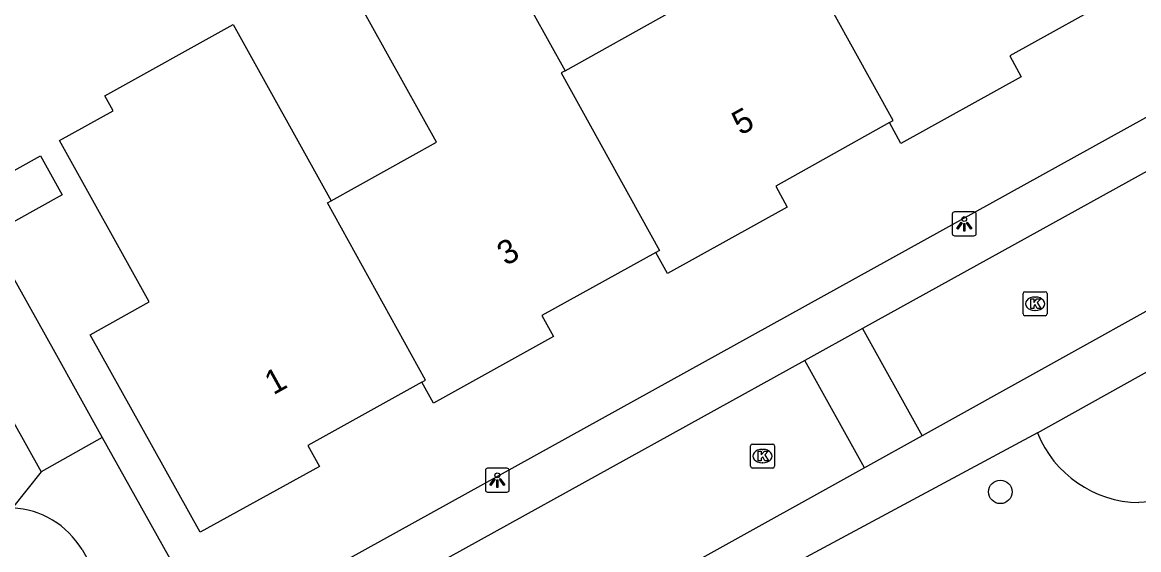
# Model space of a CAD drawing. Extents: x 159628 to 160723, y 388176 to 389416.
# Drawn here: x 160211.83 to 160258.4, y 388442.94 to 388464.92 of the extents above; entities that cross this region are included whole.
import ezdxf

# ---------------------------------------------------------------- set-up
doc = ezdxf.new("R2010")
doc.units = 0
for name, color, linetype in [('IMGEO_Boom', 7, 'Continuous'), ('IMGEO_Groenvoorziening', 7, 'Continuous'), ('IMGEO_Kolk', 7, 'Continuous'), ('IMGEO_Lichtpunt', 7, 'Continuous'), ('IMGEO_Pand', 7, 'Continuous'), ('IMGEO_Pand_nummerreeks', 7, 'Continuous'), ('IMGEO_Rijbaan_lokaal_open', 7, 'Continuous'), ('IMGEO_Voetpad_halfverhard', 7, 'Continuous'), ('IMGEO_Voetpad_open', 7, 'Continuous')]:
    doc.layers.add(name, color=color, linetype=linetype)

msp = doc.modelspace()

# ---------------------------------------------------------------- linework, layer by layer
at = {"layer": 'IMGEO_Boom'}
msp.add_circle((160252.625, 388445.345), 0.489, dxfattribs=at)
at = {"layer": 'IMGEO_Groenvoorziening'}
for points in [[(160185.435, 388468.284), (160195.231, 388450.891), (160209.082, 388458.498), (160213.193, 388451.174), (160215.17, 388447.612)], [(160182.913, 388467.038), (160193.72, 388447.443), (160200.505, 388448.02), (160208.94, 388452.771), (160212.613, 388446.186)], [(160215.17, 388447.612), (160212.613, 388446.186)], [(160215.17, 388447.612), (160219.753, 388439.417)], [(160212.613, 388446.186), (160211.422, 388444.678)], [(160270.271, 388445.647), (160264.046, 388445.253), (160258.395, 388444.896)]]:
    msp.add_lwpolyline(points, dxfattribs=at)
msp.add_arc((160258.493, 388449.56), 4.665, 202.0696, 268.7972, dxfattribs=at)
at = {"layer": 'IMGEO_Kolk'}
for p, q in [((160253.574, 388452.763), (160253.574, 388453.615)), ((160253.649, 388453.689), (160254.501, 388453.689)), ((160254.062, 388453.469), (160254.087, 388453.469)), ((160254.575, 388453.615), (160254.575, 388452.763)), ((160254.085, 388452.909), (160254.06, 388452.909)), ((160254.501, 388452.689), (160253.649, 388452.689)), ((160242.209, 388446.411), (160242.209, 388447.263)), ((160242.284, 388447.337), (160243.136, 388447.337)), ((160243.21, 388447.263), (160243.21, 388446.411)), ((160242.697, 388447.117), (160242.722, 388447.117)), ((160243.136, 388446.337), (160242.284, 388446.337)), ((160242.72, 388446.557), (160242.695, 388446.557))]:
    msp.add_line(p, q, dxfattribs=at)
for points in [[(160253.574, 388452.763), (160253.574, 388453.615)], [(160253.649, 388453.689), (160254.501, 388453.689)], [(160253.895, 388453.389), (160254.018, 388453.389), (160254.018, 388453.238), (160254.148, 388453.389), (160254.312, 388453.389), (160254.166, 388453.238), (160254.319, 388452.989), (160254.167, 388452.989), (160254.082, 388453.153), (160254.018, 388453.086), (160254.018, 388452.989), (160253.895, 388452.989), (160253.895, 388453.389)], [(160254.575, 388453.615), (160254.575, 388452.763)], [(160254.501, 388452.689), (160253.649, 388452.689)], [(160242.209, 388446.411), (160242.209, 388447.263)], [(160242.284, 388447.337), (160243.136, 388447.337)], [(160243.21, 388447.263), (160243.21, 388446.411)], [(160242.53, 388447.037), (160242.653, 388447.037), (160242.653, 388446.886), (160242.783, 388447.037), (160242.947, 388447.037), (160242.801, 388446.886), (160242.954, 388446.637), (160242.802, 388446.637), (160242.717, 388446.801), (160242.653, 388446.734), (160242.653, 388446.637), (160242.53, 388446.637), (160242.53, 388447.037)], [(160243.136, 388446.337), (160242.284, 388446.337)]]:
    msp.add_lwpolyline(points, dxfattribs=at)
for centre, start, end in [((160253.651, 388453.613), 91.552, 178.448), ((160253.651, 388453.613), 91.552, 178.448), ((160254.499, 388453.613), 1.552, 88.448), ((160254.499, 388453.613), 1.552, 88.448), ((160253.651, 388452.765), 181.552, 268.448), ((160253.651, 388452.765), 181.552, 268.448), ((160254.499, 388452.765), 271.552, 358.448), ((160254.499, 388452.765), 271.552, 358.448), ((160242.286, 388447.261), 91.552, 178.448), ((160242.286, 388447.261), 91.552, 178.448), ((160243.134, 388447.261), 1.552, 88.448), ((160243.134, 388447.261), 1.552, 88.448), ((160242.286, 388446.413), 181.552, 268.448), ((160242.286, 388446.413), 181.552, 268.448), ((160243.134, 388446.413), 271.552, 358.448), ((160243.134, 388446.413), 271.552, 358.448)]:
    msp.add_arc(centre, 0.0765, start, end, dxfattribs=at)
for centre, major_axis, ratio, start_param, end_param in [((160254.061, 388453.189), (-0.387, 0.002), 0.722429, 4.712389, 7.853982), ((160254.086, 388453.189), (-0.39, 0.002), 0.717154, 1.570796, 4.712389), ((160242.696, 388446.837), (-0.387, 0.002), 0.722429, 4.712389, 7.853982), ((160242.721, 388446.837), (-0.39, 0.002), 0.717154, 1.570796, 4.712389)]:
    msp.add_ellipse(centre, major_axis=major_axis, ratio=ratio, start_param=start_param, end_param=end_param, dxfattribs=at)
at = {"layer": 'IMGEO_Lichtpunt'}
for p, q in [((160250.622, 388456.923), (160250.622, 388456.116)), ((160250.622, 388456.923), (160250.622, 388456.116)), ((160251.524, 388457.018), (160250.716, 388457.018)), ((160251.524, 388457.018), (160250.716, 388457.018)), ((160251.618, 388456.116), (160251.618, 388456.923)), ((160251.618, 388456.116), (160251.618, 388456.923)), ((160250.716, 388456.022), (160251.524, 388456.022)), ((160250.716, 388456.022), (160251.524, 388456.022)), ((160232.048, 388446.332), (160231.24, 388446.332)), ((160232.048, 388446.332), (160231.24, 388446.332)), ((160231.146, 388446.237), (160231.146, 388445.43)), ((160231.146, 388446.237), (160231.146, 388445.43)), ((160232.142, 388445.43), (160232.142, 388446.237)), ((160232.142, 388445.43), (160232.142, 388446.237)), ((160231.24, 388445.336), (160232.048, 388445.336)), ((160231.24, 388445.336), (160232.048, 388445.336))]:
    msp.add_line(p, q, dxfattribs=at)
for points in [[(160250.996, 388456.587), (160251.035, 388456.559), (160250.847, 388456.297), (160250.809, 388456.324), (160250.996, 388456.587)], [(160251.208, 388456.559), (160251.246, 388456.586), (160251.433, 388456.324), (160251.394, 388456.296), (160251.208, 388456.559)], [(160251.098, 388456.539), (160251.145, 388456.539), (160251.145, 388456.217), (160251.098, 388456.217), (160251.098, 388456.539)], [(160231.52, 388445.901), (160231.559, 388445.873), (160231.371, 388445.611), (160231.333, 388445.638), (160231.52, 388445.901)], [(160231.622, 388445.853), (160231.669, 388445.853), (160231.669, 388445.531), (160231.622, 388445.531), (160231.622, 388445.853)], [(160231.732, 388445.873), (160231.77, 388445.9), (160231.957, 388445.638), (160231.918, 388445.61), (160231.732, 388445.873)]]:
    msp.add_lwpolyline(points, dxfattribs=at)
for centre in [(160251.121, 388456.721), (160231.645, 388446.035)]:
    msp.add_circle(centre, 0.0994, dxfattribs=at)
for centre, start, end in [((160250.716, 388456.923), 90, 180), ((160250.716, 388456.923), 90, 180), ((160251.524, 388456.923), 0, 90), ((160251.524, 388456.923), 0, 90), ((160250.716, 388456.116), 180, 270), ((160250.716, 388456.116), 180, 270), ((160251.524, 388456.116), 270, 0), ((160251.524, 388456.116), 270, 360), ((160231.24, 388446.237), 90, 180), ((160231.24, 388446.237), 90, 180), ((160232.048, 388446.237), 0, 90), ((160232.048, 388446.237), 0, 90), ((160231.24, 388445.43), 180, 270), ((160231.24, 388445.43), 180, 270), ((160232.048, 388445.43), 270, 0), ((160232.048, 388445.43), 270, 360)]:
    msp.add_arc(centre, 0.0946, start, end, dxfattribs=at)
at = {"layer": 'IMGEO_Pand'}
for points in [[(160234.472, 388462.907), (160238.859, 388465.345), (160234.778, 388472.686), (160235.666, 388473.179)], [(160224.719, 388457.486), (160229.106, 388459.924), (160225.021, 388467.274), (160230.387, 388470.256), (160234.472, 388462.907)], [(160247.996, 388460.745), (160248.153, 388460.833), (160244.058, 388468.236), (160244.215, 388468.323)], [(160257.784, 388466.184), (160253.016, 388463.525), (160253.5, 388462.65), (160248.48, 388459.87), (160247.996, 388460.745)], [(160228.495, 388449.914), (160223.747, 388447.285), (160224.23, 388446.41), (160219.25, 388443.66), (160216.821, 388448.031), (160214.67, 388451.9), (160217.128, 388453.266), (160213.388, 388459.995), (160215.623, 388461.238), (160215.278, 388461.858), (160220.634, 388464.835), (160224.719, 388457.486)], [(160234.472, 388462.907), (160234.315, 388462.82), (160238.412, 388455.411), (160238.255, 388455.324)], [(160247.996, 388460.745), (160243.255, 388458.094), (160243.74, 388457.22), (160238.74, 388454.45), (160238.255, 388455.324)], [(160212.587, 388459.354), (160213.49, 388457.73), (160210.557, 388456.1), (160209.654, 388457.725), (160212.587, 388459.354)], [(160228.495, 388449.914), (160228.652, 388450.001), (160224.562, 388457.399), (160224.719, 388457.486)], [(160238.255, 388455.324), (160233.505, 388452.694), (160233.99, 388451.82), (160228.98, 388449.04), (160228.495, 388449.914)]]:
    msp.add_lwpolyline(points, dxfattribs=at)
at = {"layer": 'IMGEO_Rijbaan_lokaal_open'}
for points in [[(160302.93, 388471.729), (160279.625, 388470.268), (160246.88, 388452.157)], [(160280.981, 388465.243), (160249.362, 388447.687)], [(160246.88, 388452.157), (160244.475, 388450.826)], [(160246.88, 388452.157), (160249.362, 388447.687)], [(160244.475, 388450.826), (160214.209, 388434.086), (160215.12, 388420.001), (160215.394, 388415.648)], [(160246.959, 388446.352), (160244.475, 388450.826)], [(160249.362, 388447.687), (160246.959, 388446.352)], [(160246.959, 388446.352), (160219.445, 388431.075), (160220.428, 388415.979)]]:
    msp.add_lwpolyline(points, dxfattribs=at)
at = {"layer": 'IMGEO_Voetpad_halfverhard'}
msp.add_lwpolyline([(160214.326, 388442.939), (160217.097, 388437.947)], dxfattribs=at)
msp.add_arc((160211.235, 388441.071), 3.611, 31.1402, 87.031, dxfattribs=at)
at = {"layer": 'IMGEO_Voetpad_open'}
for points in [[(160219.753, 388439.417), (160289.692, 388478.113)], [(160254.17, 388447.807), (160281.401, 388462.982)], [(160254.17, 388447.807), (160236.708, 388438.431)]]:
    msp.add_lwpolyline(points, dxfattribs=at)

# ---------------------------------------------------------------- texts
at = {"layer": 'IMGEO_Pand_nummerreeks'}
for s, rotation, p in [('5', 29.049, (160241.792, 388460.19)), ('3', 29.0484, (160231.998, 388454.75)), ('1', 29.049, (160222.303, 388449.367))]:
    msp.add_text(s, height=1, rotation=rotation, dxfattribs=at).set_placement(p)

doc.saveas('drawing.dxf')
